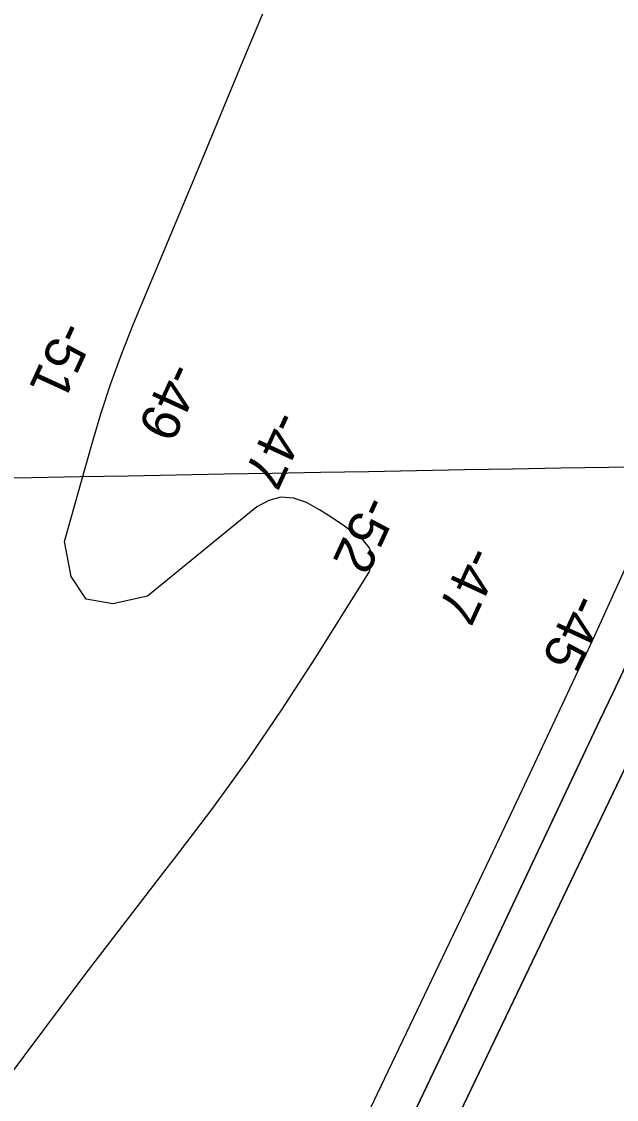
# Model space of a CAD drawing. Extents: x 3930721 to 3950824, y 220441 to 242861.
# Drawn here: x 3941164 to 3941678, y 229688 to 230620 of the extents above; entities that cross this region are included whole.
import ezdxf

# ---------------------------------------------------------------- set-up
doc = ezdxf.new("R2010")
doc.units = 0
for name, color, linetype in [('V-GRID-MAJR', 7, 'Continuous'), ('V-RIVR-RANG', 7, 'Continuous'), ('V-TOPO-DPTH', 7, 'Continuous'), ('V-TOPO-MAJR', 7, 'Continuous'), ('V-TOPO-MINR', 7, 'Continuous')]:
    doc.layers.add(name, color=color, linetype=linetype)

msp = doc.modelspace()

# ---------------------------------------------------------------- linework, layer by layer
at = {"layer": 'V-GRID-MAJR'}
msp.add_spline([(3935736.57, 230127.92), (3940756.95, 230218.14), (3946078.33, 230314.51), (3946614.64, 230324.26)], degree=3, dxfattribs=at)
at = {"layer": 'V-TOPO-DPTH'}
for points in [[(3942453.94, 231845.49), (3942443.28, 231814.02), (3942390.36, 231660.37), (3942352.9, 231552.19), (3942315.21, 231444.09), (3942277.15, 231336.12), (3942238.86, 231228.23), (3942137.57, 230944.34), (3942135.16, 230937.87), (3942132.63, 230931.44), (3942129.94, 230925.08), (3942127.13, 230918.77), (3941921.02, 230472.26), (3941888.03, 230401.15), (3941854.86, 230330.13), (3941821.41, 230259.23), (3941787.78, 230188.42), (3941758.75, 230127.62), (3941739.48, 230087.28), (3941720.2, 230046.95), (3941700.91, 230006.63), (3941681.59, 229966.31), (3941338.17, 229249.76)], [(3941491.13, 229651.31), (3941540.05, 229754), (3941663.91, 230015.76), (3941674.95, 230039.2), (3941685.95, 230062.66), (3941696.86, 230086.16), (3941707.73, 230109.68), (3941874.25, 230471.62), (3941910.6, 230551.44), (3941946.54, 230631.45), (3941981.84, 230711.73), (3942016.74, 230792.2), (3942061.5, 230896.56), (3942073.54, 230925.06), (3942085.35, 230953.64), (3942096.84, 230982.36), (3942108.11, 231011.17), (3942154.08, 231130.66), (3942187.75, 231219.44), (3942220.84, 231308.43), (3942253.08, 231397.73), (3942284.75, 231487.24), (3942410.72, 231848.72)], [(3942410.72, 231848.72), (3942284.75, 231487.24), (3942253.08, 231397.73), (3942220.84, 231308.43), (3942187.75, 231219.44), (3942154.08, 231130.66), (3942108.11, 231011.17), (3942096.84, 230982.36), (3942085.35, 230953.64), (3942073.54, 230925.06), (3942061.5, 230896.56), (3942016.74, 230792.2), (3941981.84, 230711.73), (3941946.54, 230631.45), (3941910.6, 230551.44), (3941874.25, 230471.62), (3941707.73, 230109.68), (3941696.86, 230086.16), (3941685.95, 230062.66), (3941674.95, 230039.2), (3941663.91, 230015.76), (3941540.05, 229754), (3941491.13, 229651.31)], [(3941221.82, 229171.53), (3941534.21, 229824.03), (3941554.33, 229866.17), (3941574.39, 229908.34), (3941594.36, 229950.55), (3941614.26, 229992.8), (3941646.96, 230062.37), (3941650.46, 230069.85), (3941653.94, 230077.34), (3941657.4, 230084.85), (3941660.83, 230092.36), (3941693.43, 230163.95), (3941712.96, 230207.34), (3941732.26, 230250.84), (3941751.19, 230294.49), (3941769.88, 230338.26), (3942035.02, 230966.39)], [(3941221.82, 229171.53), (3941534.21, 229824.03), (3941554.33, 229866.17), (3941574.39, 229908.34), (3941594.36, 229950.55), (3941614.26, 229992.8), (3941646.96, 230062.37), (3941650.46, 230069.85), (3941653.94, 230077.34), (3941657.4, 230084.85), (3941660.83, 230092.36), (3941693.43, 230163.95), (3941712.96, 230207.34), (3941732.26, 230250.84), (3941751.19, 230294.49), (3941769.88, 230338.26), (3942035.02, 230966.39)]]:
    msp.add_lwpolyline(points, dxfattribs=at)
at = {"layer": 'V-TOPO-MAJR'}
msp.add_lwpolyline([(3941148.95, 229702.79), (3941183.65, 229749.54), (3941218.63, 229796.08), (3941254.03, 229842.3), (3941289.7, 229888.31), (3941296.08, 229896.46), (3941328.1, 229938.71), (3941359.23, 229981.6), (3941389, 230025.43), (3941417.88, 230069.89), (3941464.28, 230143.82), (3941466.76, 230151.34), (3941467.12, 230158.47), (3941464.3, 230165.04), (3941459.37, 230171.22), (3941453.46, 230175.77), (3941442.99, 230183.43), (3941432.31, 230190.76), (3941421.3, 230197.58), (3941410.07, 230204.07), (3941398.92, 230207.67), (3941388, 230208.65), (3941377.45, 230205.7), (3941367.14, 230200.13), (3941272.62, 230123.13), (3941242.59, 230116.5), (3941219.46, 230120.4), (3941206.68, 230140.07), (3941200.81, 230170.26), (3941224.41, 230254.12), (3941232.36, 230280.54), (3941240.94, 230306.75), (3941250.46, 230332.63), (3941260.61, 230358.3), (3941315.75, 230490.71), (3941353.98, 230582.4), (3941392.26, 230674.07)], dxfattribs=at)
at = {"layer": 'V-TOPO-MINR'}
for points in [[(3941338.17, 229249.76), (3941681.59, 229966.31), (3941700.91, 230006.63), (3941720.2, 230046.95), (3941739.48, 230087.28), (3941758.75, 230127.62), (3941787.78, 230188.42), (3941821.41, 230259.23), (3941854.86, 230330.13), (3941888.03, 230401.15), (3941921.02, 230472.26), (3942127.13, 230918.77), (3942129.94, 230925.08), (3942132.63, 230931.44), (3942135.16, 230937.87), (3942137.57, 230944.34), (3942238.86, 231228.23), (3942277.15, 231336.12), (3942315.21, 231444.09), (3942352.9, 231552.19), (3942390.36, 231660.37), (3942443.28, 231814.02), (3942453.94, 231845.49)], [(3941491.13, 229651.31), (3941540.05, 229754), (3941663.91, 230015.76), (3941674.95, 230039.2), (3941685.95, 230062.66), (3941696.86, 230086.16), (3941707.73, 230109.68), (3941874.25, 230471.62), (3941910.6, 230551.44), (3941946.54, 230631.45), (3941981.84, 230711.73), (3942016.74, 230792.2), (3942061.5, 230896.56), (3942073.54, 230925.06), (3942085.35, 230953.64), (3942096.84, 230982.36), (3942108.11, 231011.17), (3942154.08, 231130.66), (3942187.75, 231219.44), (3942220.84, 231308.43), (3942253.08, 231397.73), (3942284.75, 231487.24), (3942410.72, 231848.72)], [(3941221.82, 229171.53), (3941534.21, 229824.03), (3941554.33, 229866.17), (3941574.39, 229908.34), (3941594.36, 229950.55), (3941614.26, 229992.8), (3941646.96, 230062.37), (3941650.46, 230069.85), (3941653.94, 230077.34), (3941657.4, 230084.85), (3941660.83, 230092.36), (3941693.43, 230163.95), (3941712.96, 230207.34), (3941732.26, 230250.84), (3941751.19, 230294.49), (3941769.88, 230338.26), (3942035.02, 230966.39)]]:
    msp.add_lwpolyline(points, dxfattribs=at)

# ---------------------------------------------------------------- texts
at = {"layer": 'V-RIVR-RANG'}
for s, rotation, p in [('-51', 245.35769, (3941196.86, 230362.86)), ('-49', 245.35769, (3941290.87, 230327.25)), ('-47', 245.35769, (3941381.81, 230285.66)), ('-52', 245.21833, (3941459.39, 230212.34)), ('-47', 245.21833, (3941549.28, 230168.49)), ('-45', 245.21833, (3941640.51, 230127.51))]:
    msp.add_text(s, height=33.5, rotation=rotation, dxfattribs=at).set_placement(p)

doc.saveas('drawing.dxf')
